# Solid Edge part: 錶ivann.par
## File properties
Author: KULL
Template: Iso Metric Part.par
Last saved by: KULL
Revision: 5
Application: Solid Edge
Accuracy: 0,990
Face Style: Model Default
Fill Style: Normal
Coef. of Thermal Exp: 0.0
Thermal Conductivity: 0.0
Specific Heat: 0.0
Modulus of Elasticity: 0.0
Poisson's Ratio: 0.0
Yield Stress: 0.0
Ultimate Stress: 0.0
Elongation: 0.0
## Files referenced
..\Mootor_ASM_1.asm
ikkega.par
lG:\Haapsalu Kolledz\Solid edge leong\Solid edge Sync practice\ROVER_Heiko_Kull_EKSAM\Mootor\Mootor_ASM_1.asm
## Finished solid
Body 1: solid body, 145 faces, 331 edges, 192 vertices.
  Faces by surface: cylinder 52, blend 51, plane 30, swept 8, torus 4
  Edges by curve: line 130, circle 88, intersection 53, ellipse 52, spline 8
Body 2: sheet body, 1 face, 52 edges, 52 vertices.
  Faces by surface: plane 1
  Edges by curve: line 26, circle 14, ellipse 4, intersection 4, spline 4
Bounding box of the edges (mm; curved faces can reach further): 94.000 x 35.239 x 17.090, from (-47, -17.6197, -13.4464) to (47, 17.6197, 3.6435).
Cylindrical faces by radius (mm): R0.2 x4, R0.6 x4, R0.8 x4, R1 x4, R1.4 x4, R1.6 x2, R1.8 x4, R2 x2, R2.6 x4, R3 x8, R3.4 x4, R3.6 x4, R4 x4
Toroidal faces (ring radius, tube radius in mm): R3.4 r1.4 x2, R3.4 r1.8 x2
Planar faces by outward normal: +x 2, +y 4, +z 3, -x 2, -y 4, -z 3, oblique 12
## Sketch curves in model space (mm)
line (27, -15.3992, 3.6435) -> (-27, -15.3992, 3.6435)
line (26, -15.3992, 3.6435) -> (28, -15.3992, 3.6435)
line (-28, -15.3992, 3.6435) -> (-26, -15.3992, 3.6435)
line (-26, 16.375, 3.6435) -> (-26, 14.4233, 3.6435)
line (-28, 16.375, 3.6435) -> (-28, 14.4233, 3.6435)
line (-8, 16.375, 3.6435) -> (-8, 14.4233, 3.6435)
line (-10, 16.375, 3.6435) -> (-10, 14.4233, 3.6435)
line (10, 16.375, 3.6435) -> (10, 14.4233, 3.6435)
line (8, 16.375, 3.6435) -> (8, 14.4233, 3.6435)
line (28, 16.375, 3.6435) -> (28, 14.4233, 3.6435)
line (26, 16.375, 3.6435) -> (26, 14.4233, 3.6435)
line (28, -14.4233, 3.6435) -> (28, -16.375, 3.6435)
line (26, -14.4233, 3.6435) -> (26, -16.375, 3.6435)
line (10, -14.4233, 3.6435) -> (10, -16.375, 3.6435)
line (8, -14.4233, 3.6435) -> (8, -16.375, 3.6435)
line (-8, -14.4233, 3.6435) -> (-8, -16.375, 3.6435)
line (-10, -14.4233, 3.6435) -> (-10, -16.375, 3.6435)
line (-26, -14.4233, 3.6435) -> (-26, -16.375, 3.6435)
line (-28, -14.4233, 3.6435) -> (-28, -16.375, 3.6435)
circle centre (-27, -15.3992, 3.6435) radius 1.4
spline (40, 14.2197, 3.6435) -> (42.5307, 13.1599, 3.6435) -> (43.6, 10.52, 3.6435)
line (43.6, 10.52, 3.6435) -> (43.6, -10.52, 3.6435)
spline (43.6, -10.52, 3.6435) -> (42.5307, -13.1599, 3.6435) -> (40, -14.2197, 3.6435)
line (40, -14.2197, 3.6435) -> (-40, -14.2197, 3.6435)
spline (-40, -14.2197, 3.6435) -> (-42.5307, -13.1599, 3.6435) -> (-43.6, -10.52, 3.6435)
line (-43.6, -10.52, 3.6435) -> (-43.6, 10.52, 3.6435)
spline (-43.6, 10.52, 3.6435) -> (-42.5307, 13.1599, 3.6435) -> (-40, 14.2197, 3.6435)
line (-40, 14.2197, 3.6435) -> (40, 14.2197, 3.6435)
spline (40, 17.6197, 3.6435) -> (44.9475, 15.5469, 3.6435) -> (47, 10.52, 3.6435)
line (47, 10.52, 3.6435) -> (47, -10.52, 3.6435)
spline (47, -10.52, 3.6435) -> (44.9475, -15.5469, 3.6435) -> (40, -17.6197, 3.6435)
line (40, -17.6197, 3.6435) -> (-40, -17.6197, 3.6435)
spline (-40, -17.6197, 3.6435) -> (-44.9475, -15.5469, 3.6435) -> (-47, -10.52, 3.6435)
line (-47, -10.52, 3.6435) -> (-47, 10.52, 3.6435)
spline (-47, 10.52, 3.6435) -> (-44.9475, 15.5469, 3.6435) -> (-40, 17.6197, 3.6435)
line (-40, 17.6197, 3.6435) -> (40, 17.6197, 3.6435)
spline (-45, 10.52, 3.6435) -> (-43.5265, 14.1432, 3.6435) -> (-40, 15.6197, 3.6435)
line (-40, 15.6197, 3.6435) -> (40, 15.6197, 3.6435)
spline (40, 15.6197, 3.6435) -> (43.5265, 14.1432, 3.6435) -> (45, 10.52, 3.6435)
line (45, 10.52, 3.6435) -> (45, -10.52, 3.6435)
spline (45, -10.52, 3.6435) -> (43.5265, -14.1432, 3.6435) -> (40, -15.6197, 3.6435)
line (40, -15.6197, 3.6435) -> (-40, -15.6197, 3.6435)
spline (-40, -15.6197, 3.6435) -> (-43.5265, -14.1432, 3.6435) -> (-45, -10.52, 3.6435)
line (-45, -10.52, 3.6435) -> (-45, 10.52, 3.6435)
line (-47, 10.5199, 2.4435) -> (-47, -10.5199, 2.4435)
spline (-47, 10.5199, 2.4435) -> (-44.9475, 15.5468, 2.4435) -> (-40, 17.6197, 2.4435)
line (40, 17.6197, 2.4435) -> (-40, 17.6197, 2.4435)
spline (40, 17.6197, 2.4435) -> (44.9475, 15.5468, 2.4435) -> (47, 10.5199, 2.4435)
line (47, -10.5199, 2.4435) -> (47, 10.5199, 2.4435)
spline (47, -10.5199, 2.4435) -> (44.9475, -15.5468, 2.4435) -> (40, -17.6197, 2.4435)
line (-40, -17.6197, 2.4435) -> (40, -17.6197, 2.4435)
spline (-40, -17.6197, 2.4435) -> (-44.9475, -15.5468, 2.4435) -> (-47, -10.5199, 2.4435)
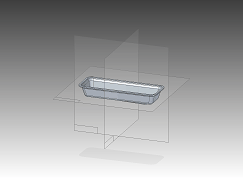
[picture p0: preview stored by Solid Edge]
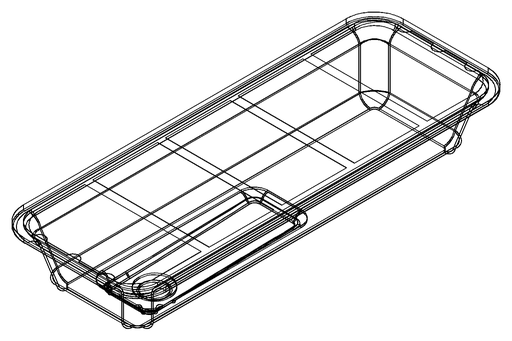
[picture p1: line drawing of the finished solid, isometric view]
